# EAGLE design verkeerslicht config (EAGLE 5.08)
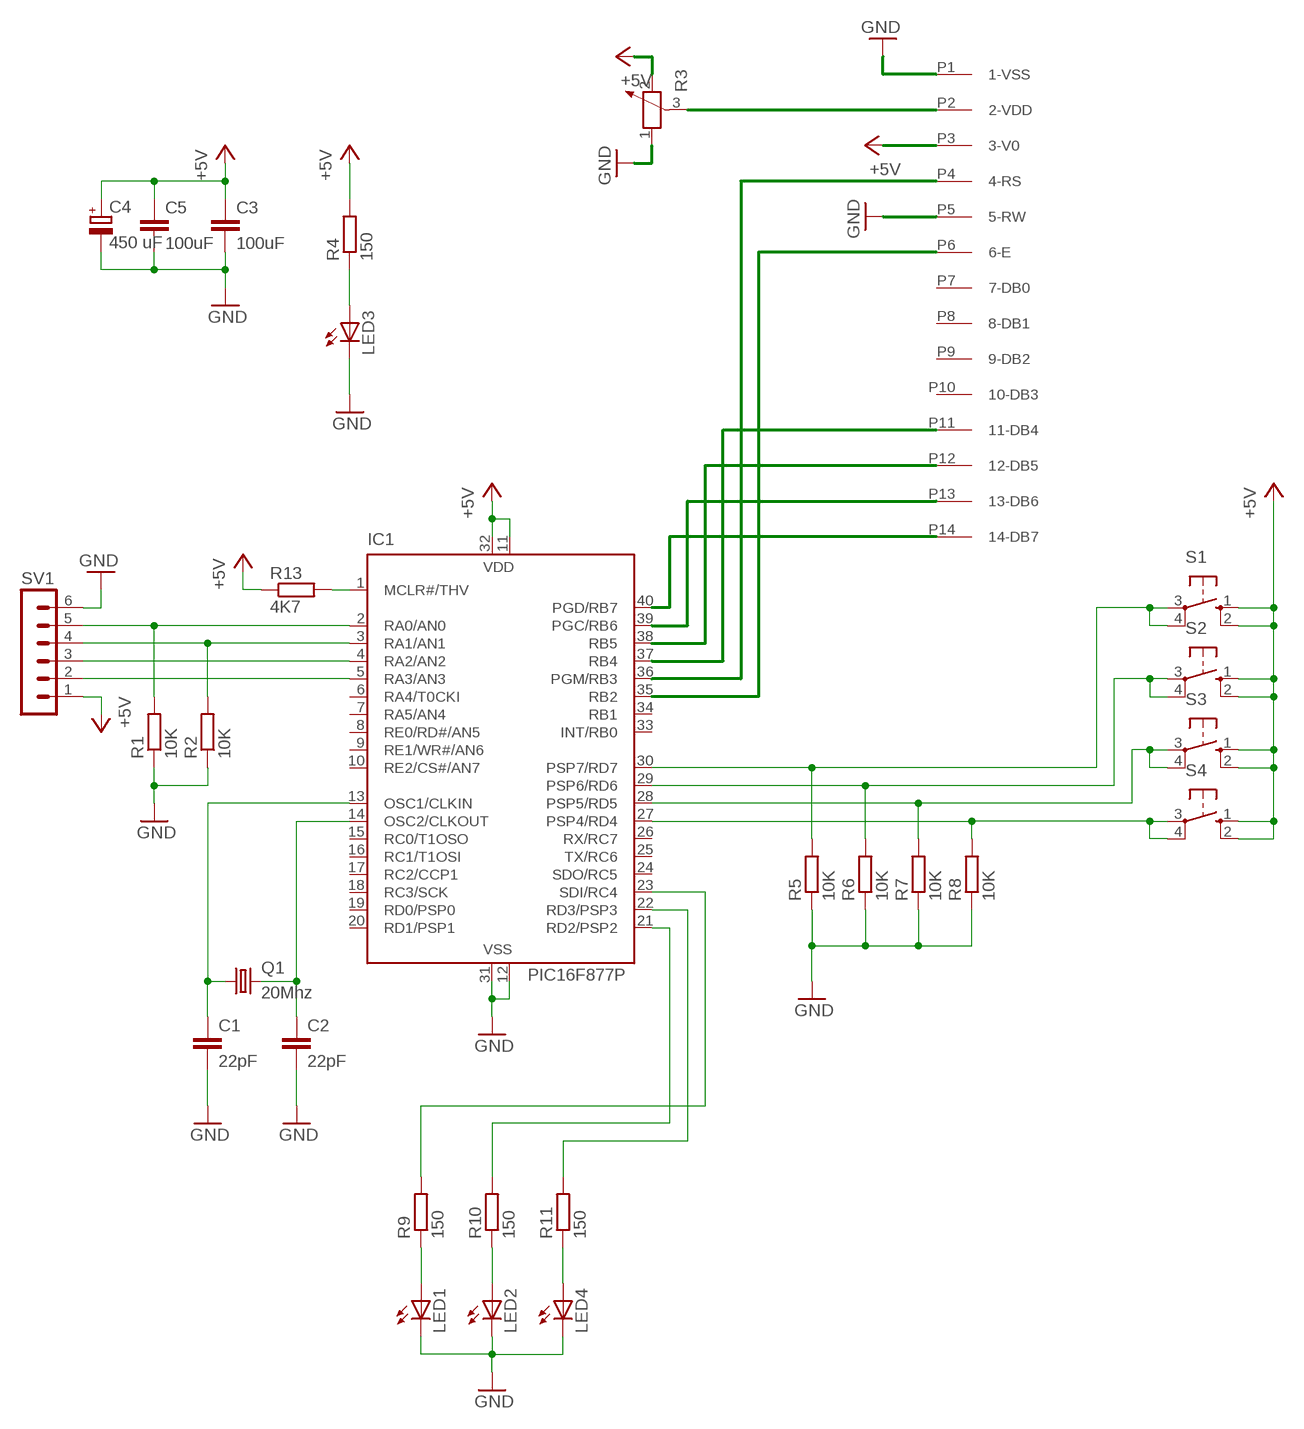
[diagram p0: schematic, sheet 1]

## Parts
C1  22pF  C-EU050-025X075  [C050-025X075]
C2  22pF  C-EU050-025X075  [C050-025X075]
C3  100uF  C-EU050-025X075  [C050-025X075]
C4  450 uF  CPOL-EUE5-13  [E5-13]
C5  100uF  C-EU050-025X075  [C050-025X075]
IC1  PIC16F877P  [DIL40]
LED1  LED3MM  [LED3MM]
LED2  LED3MM  [LED3MM]
LED3  LED3MM  [LED3MM]
LED4  LED3MM  [LED3MM]
Q1  20Mhz  CRYSTALHC18U-V  [HC18U-V]
R1  10K  R-EU_0207/7  [0207/7]
R2  10K  R-EU_0207/7  [0207/7]
R3  POTENTIOMETER_PT-10S  [PT-10S]
R4  150  R-EU_0207/7  [0207/7]
R5  10K  R-EU_0207/7  [0207/7]
R6  10K  R-EU_0207/7  [0207/7]
R7  10K  R-EU_0207/7  [0207/7]
R8  10K  R-EU_0207/7  [0207/7]
R9  150  R-EU_0207/2V  [0207/2V]
R10  150  R-EU_0207/2V  [0207/2V]
R11  150  R-EU_0207/2V  [0207/2V]
R13  4K7  R-EU_0207/10  [0207/10]
S1  10-XX  [B3F-10XX]
S2  10-XX  [B3F-10XX]
S3  10-XX  [B3F-10XX]
S4  10-XX  [B3F-10XX]
SV1  MA06-1  [MA06-1]
U$1  16X2LCD  [NO_BACKLIGHT]

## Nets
+5V: C3.1 C4.+ C5.1 IC1.11(VDD) IC1.32(VDD) R3.2 R4.2 R13.1 S1.1(S) S1.2(S1) S2.1(S) S2.2(S1) S3.1(S) S3.2(S1) S4.1(S) S4.2(S1) SV1.1 U$1.P3(3-V0)
GND: C1.2 C2.2 C3.2 C4.- C5.2 IC1.12(VSS) IC1.31(VSS) LED1.K(C) LED2.K(C) LED3.K(C) LED4.K(C) R1.1 R2.1 R3.1 R5.1 R6.1 R7.1 R8.1 SV1.6 U$1.P1(1-VSS) U$1.P5(5-RW)
N$1: IC1.23(SDI/RC4) R9.2
N$2: IC1.30(PSP7/RD7) R5.2 S1.3(P) S1.4(P1)
N$3: IC1.29(PSP6/RD6) R6.2 S2.3(P) S2.4(P1)
N$4: IC1.28(PSP5/RD5) R7.2 S3.3(P) S3.4(P1)
N$5: IC1.27(PSP4/RD4) R8.2 S4.3(P) S4.4(P1)
N$6: IC1.40(PGD/RB7) U$1.P14(14-DB7)
N$7: IC1.39(PGC/RB6) U$1.P13(13-DB6)
N$8: IC1.38(RB5) U$1.P12(12-DB5)
N$9: C1.1 IC1.13(OSC1/CLKIN) Q1.1
N$10: IC1.37(RB4) U$1.P11(11-DB4)
N$11: IC1.36(PGM/RB3) U$1.P4(4-RS)
N$12: IC1.35(RB2) U$1.P6(6-E)
N$13: R3.3 U$1.P2(2-VDD)
N$30: C2.1 IC1.14(OSC2/CLKOUT) Q1.2
N$31: IC1.1(MCLR#/THV) R13.2
N$33: IC1.21(RD2/PSP2) R10.2
N$34: LED3.A R4.1
N$35: LED1.A R9.1
N$36: LED2.A R10.1
N$53: IC1.2(RA0/AN0) R1.2 SV1.5
N$54: IC1.3(RA1/AN1) R2.2 SV1.4
N$55: IC1.4(RA2/AN2) SV1.3
N$56: IC1.5(RA3/AN3) SV1.2
N$72: LED4.A R11.1
N$73: IC1.22(RD3/PSP3) R11.2
Unconnected: IC1.6(RA4/T0CKI) IC1.7(RA5/AN4) IC1.8(RE0/RD#/AN5) IC1.9(RE1/WR#/AN6) IC1.10(RE2/CS#/AN7) IC1.15(RC0/T1OSO) IC1.16(RC1/T1OSI) IC1.17(RC2/CCP1) IC1.18(RC3/SCK) IC1.19(RD0/PSP0) IC1.20(RD1/PSP1) IC1.24(SDO/RC5) IC1.25(TX/RC6) IC1.26(RX/RC7) IC1.33(INT/RB0) IC1.34(RB1) U$1.P7(7-DB0) U$1.P8(8-DB1) U$1.P9(9-DB2) U$1.P10(10-DB3)

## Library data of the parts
C1-C3 C5 = rcl:C-EU: CAPACITOR, European symbol
C4 = rcl:CPOL-EU: POLARIZED CAPACITOR, European symbol
IC1 = microchip:PIC16F87*: MICROCONTROLLER
LED1-LED4 = led:LED: LED
Q1 = crystal:CRYSTAL: CRYSTAL
R1 R2 R4-R11 R13 = rcl:R-EU_: RESISTOR, European symbol
R3 = rcl:POTENTIOMETER_: Potentiometer
S1-S4 = switch-omron:10-XX: OMRON SWITCH
SV1 = con-lstb:MA06-1: PIN HEADER
U$1 = lcd_nobacklight:16X2LCD: 16x2 LCD - no backlight

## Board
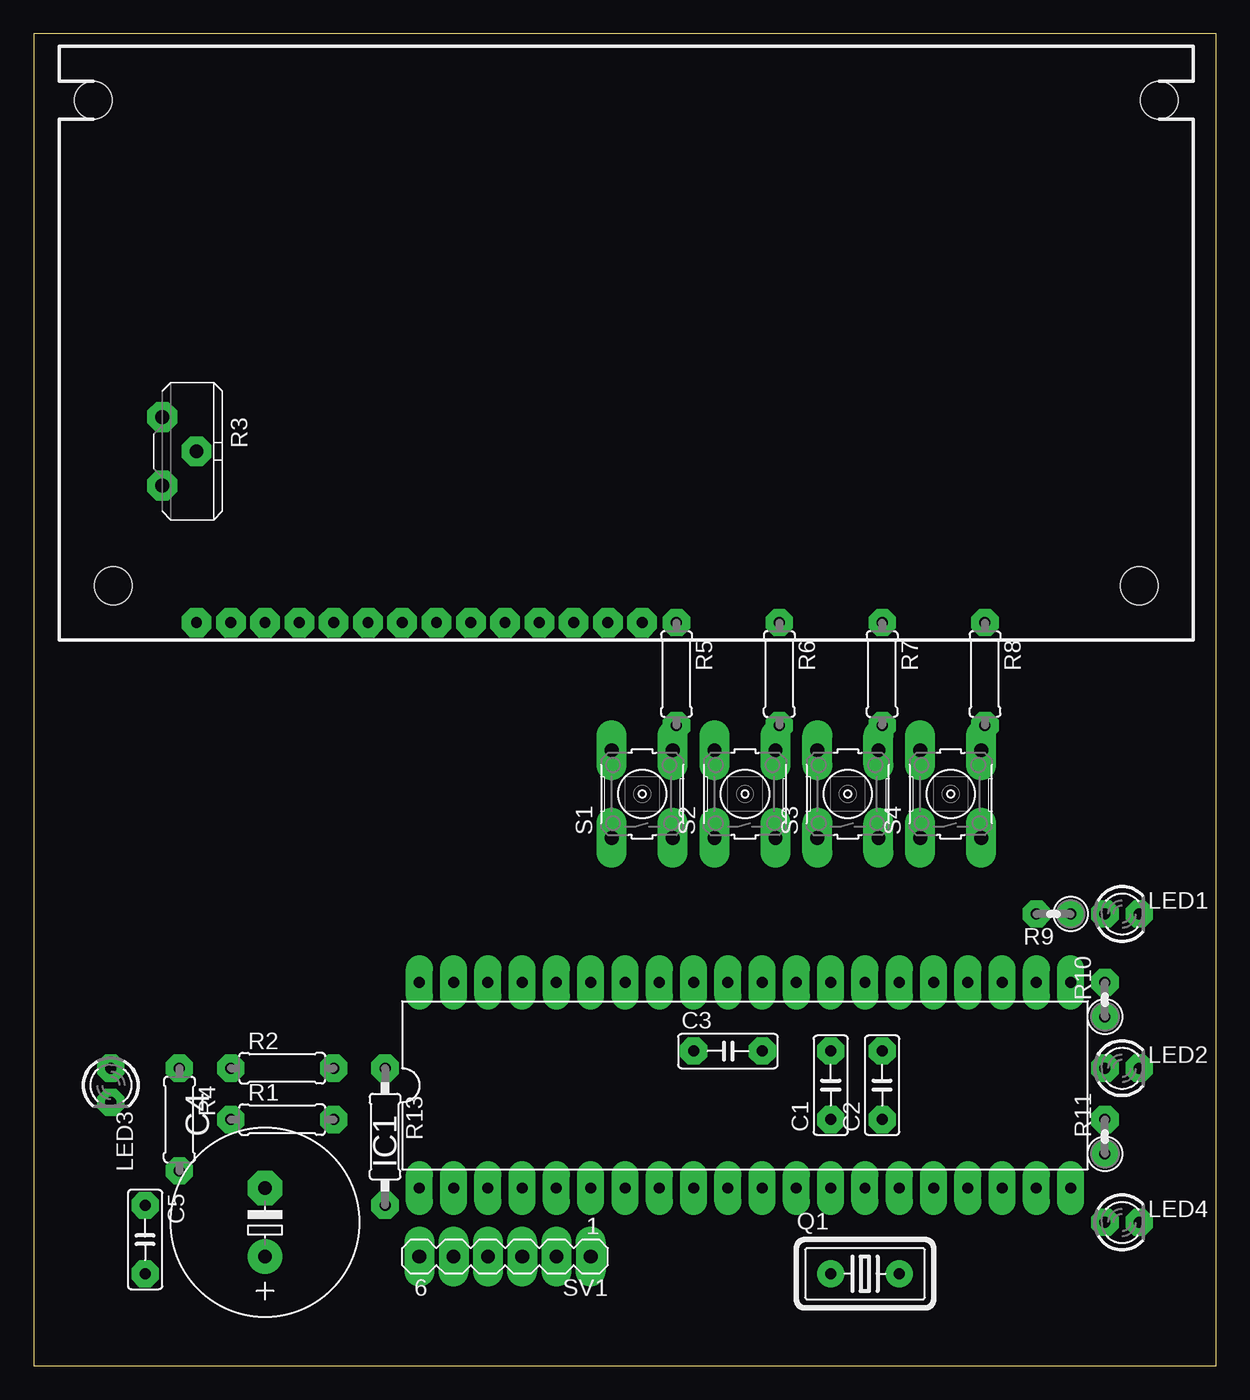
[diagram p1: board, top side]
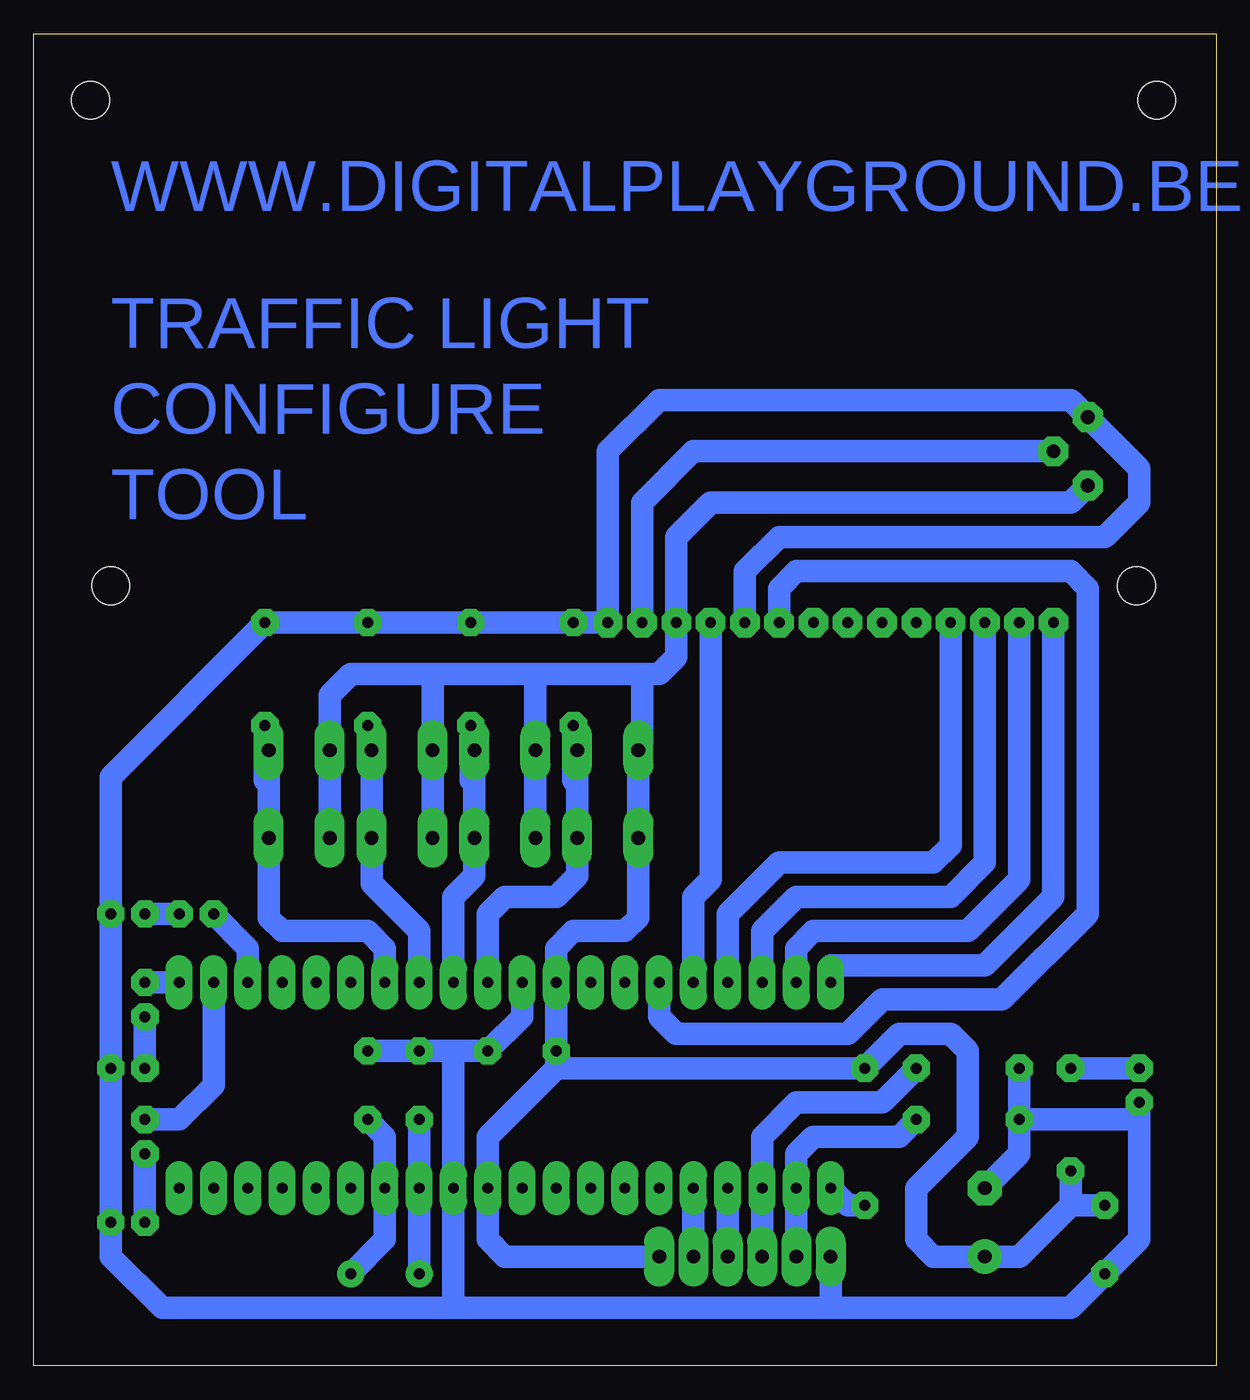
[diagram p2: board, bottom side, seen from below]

Size 87.61 x 98.73 mm. Coordinates in mm from the lower left corner, seen from the top.
Outline: 0,0 87.61,0 87.61,98.73 0,98.73 0,0
Copper layers (1*16): Top 1mm / dielectric 1.5mm / Bottom 1mm
Design rules "DRC settings middle": minimum track width 1.2mm, minimum drill 24mil, track to track 0.4mm, track to pad 0.4mm, pad to pad 0.4mm, via to via 0.4mm, smd to smd 8mil, copper to edge 0.5mm, drill to drill 0.5mm, minimum pad ring 0.6mm, minimum via ring 1mm, stop-mask expansion 4mil, vias tented up to drill 0mil, thermal gap 10mil

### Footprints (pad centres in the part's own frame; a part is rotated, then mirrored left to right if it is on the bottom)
C050-025X075 = drill 0.813 octagon: 1 -2.54,0; 2 2.54,0
E5-13 = drill 1.016 pad 2.54 round: + -2.54,0 | drill 1.016 pad 2.54 octagon: - 2.54,0
DIL40 = drill 0.813 long: 1 -24.13,-7.62; 2 -21.59,-7.62; 3 -19.05,-7.62; 4 -16.51,-7.62; 5 -13.97,-7.62; 6 -11.43,-7.62; 7 -8.89,-7.62; 8 -6.35,-7.62; 9 -3.81,-7.62; 10 -1.27,-7.62; 11 1.27,-7.62; 12 3.81,-7.62; 13 6.35,-7.62; 14 8.89,-7.62; 15 11.43,-7.62; 16 13.97,-7.62; 17 16.51,-7.62; 18 19.05,-7.62; 19 21.59,-7.62; 20 24.13,-7.62; 21 24.13,7.62; 22 21.59,7.62; 23 19.05,7.62; 24 16.51,7.62; 25 13.97,7.62; 26 11.43,7.62; 27 8.89,7.62; 28 6.35,7.62; 29 3.81,7.62; 30 1.27,7.62; 31 -1.27,7.62; 32 -3.81,7.62; 33 -6.35,7.62; 34 -8.89,7.62; 35 -11.43,7.62; 36 -13.97,7.62; 37 -16.51,7.62; 38 -19.05,7.62; 39 -21.59,7.62; 40 -24.13,7.62
LED3MM = drill 0.813 octagon: A -1.27,0; K 1.27,0
HC18U-V = drill 0.813 round: 1 -2.54,0; 2 2.54,0
0207/7 = drill 0.813 octagon: 1 -3.81,0; 2 3.81,0
PT-10S = drill 1.016 pad 1.778 octagon: 1 -2.54,-1.27; 2 2.54,-1.27; 3 0,1.27
0207/2V = drill 0.813 octagon: 1 -1.27,0; 2 1.27,0
0207/10 = drill 0.813 octagon: 1 -5.08,0; 2 5.08,0
B3F-10XX = drill 1.016 long: 1 -3.251,2.261; 2 3.251,2.261; 3 -3.251,-2.261; 4 3.251,-2.261
MA06-1 = drill 1.016 long: 1 -6.35,0; 2 -3.81,0; 3 -1.27,0; 4 1.27,0; 5 3.81,0; 6 6.35,0
NO_BACKLIGHT = drill 0.8 pad 2.184 octagon: P1 43.18,1.27; P2 40.64,1.27; P3 38.1,1.27; P4 35.56,1.27; P5 33.02,1.27; P6 30.48,1.27; P7 27.94,1.27; P8 25.4,1.27; P9 22.86,1.27; P10 20.32,1.27; P11 17.78,1.27; P12 15.24,1.27; P13 12.7,1.27; P14 10.16,1.27 | hole 2.8: 4,4; 80,4; 2.5,40; 81.5,40

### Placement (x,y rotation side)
C1  59.05,20.79 90 top
C2  62.86,20.79 90 top
C3  51.43,23.33 0 top
C4  17.14,10.63 90 top
C5  8.25,9.36 270 top
IC1  52.7,20.79 0 top
LED1  80.64,33.49 0 top
LED2  80.64,22.06 0 top
LED3  5.71,20.79 270 top
LED4  80.64,10.63 0 top
Q1  61.59,6.82 0 top
R1  18.41,18.25 0 top
R2  18.41,22.06 0 top
R3  10.79,67.78 270 top
R4  10.79,18.25 270 top
R5  47.62,51.27 270 top
R6  55.24,51.27 270 top
R7  62.86,51.27 270 top
R8  70.48,51.27 270 top
R9  75.56,33.49 180 top
R10  79.37,27.14 90 top
R11  79.37,16.98 90 top
R13  26.03,16.98 270 top
S1  45.08,42.38 90 top
S2  52.7,42.38 90 top
S3  60.32,42.38 90 top
S4  67.94,42.38 90 top
SV1  34.92,8.09 180 top
U$1  1.9,53.81 0 top

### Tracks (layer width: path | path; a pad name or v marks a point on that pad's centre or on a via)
+5V
  Bottom 1.676: SV1.1 52.7,8.09 53.97,9.36 IC1.11 53.97,16.98 48.89,22.06 | S2.1 S2.2 50.44,50.99 50.16,51.27 | S4.1 S4.2 65.68,49.72 64.13,51.27 57.78,51.27 | 10.79,11.9 14.6,8.09 C4.+ 20.95,8.09 22.22,9.36 22.22,13.17 18.41,16.98 18.41,23.33 19.68,24.6 23.49,24.6 R13.1 48.89,22.06 | C5.1 10.79,11.9 | 10.79,11.9 R4.2 | 48.89,22.06 C3.1 IC1.32 48.89,30.95 47.62,32.22 43.81,32.22 42.82,33.21 S1.1 S1.2 42.82,45.91 42.54,46.19 42.54,51.27 | 42.54,51.27 50.16,51.27 | 50.16,51.27 57.78,51.27 | 42.54,51.27 41.27,51.27 40,52.54 U$1.P3 40,61.43 37.46,63.97 10.79,63.97 R3.2 | 57.78,51.27 58.06,50.99 S3.2 S3.1
GND
  Bottom 1.676: IC1.31 51.43,25.87 C3.2 56.51,23.33 | 56.51,23.33 C1.2 C2.2 | 56.51,23.33 IC1.12 56.51,4.28 | R1.1 R2.1 | 28.57,4.28 56.51,4.28 | 56.51,4.28 78.1,4.28 81.91,8.09 LED4.K LED2.K LED1.K 81.91,43.65 R8.1 R7.1 R6.1 R5.1 U$1.P1 45.08,67.78 41.27,71.59 10.79,71.59 R3.1 5.71,66.51 5.71,63.97 8.25,61.43 32.38,61.43 34.92,58.89 U$1.P5 | 28.57,4.28 10.79,4.28 C5.2 5.71,9.36 5.71,18.25 | 28.57,4.28 SV1.6 | 5.71,18.25 LED3.K | 5.71,18.25 R1.1 | C4.- 14.6,15.71 R1.1
N$1
  Bottom 1.676: IC1.23 71.75,30.95 R9.2
N$2
  Bottom 1.676: IC1.30 53.97,33.49 52.7,34.76 48.89,34.76 47.34,36.31 S1.3 S1.4 47.62,43.37 R5.2
N$3
  Bottom 1.676: IC1.29 56.51,34.76 54.96,36.31 S2.3 S2.4 55.24,43.37 R6.2
N$4
  Bottom 1.676: IC1.28 59.05,32.22 62.58,35.75 S3.3 S3.4 62.58,47.18 R7.2
N$5
  Bottom 1.676: IC1.27 61.59,30.95 62.86,32.22 69.21,32.22 70.2,33.21 S4.3 S4.4 70.48,43.37 R8.2
N$6
  Bottom 1.676: U$1.P14 12.06,34.76 17.14,29.68 28.57,29.68 IC1.40
N$7
  Bottom 1.676: IC1.39 31.11,30.95 29.84,32.22 18.41,32.22 14.6,36.03 U$1.P13
N$8
  Bottom 1.676: IC1.38 33.65,32.22 31.11,34.76 19.68,34.76 17.14,37.3 U$1.P12
N$9
  Bottom 1.676: C1.1 IC1.13 59.05,9.36 Q1.1
N$10
  Bottom 1.676: IC1.37 36.19,33.49 32.38,37.3 20.95,37.3 19.68,38.57 U$1.P11
N$11
  Bottom 1.676: IC1.36 38.73,34.76 37.46,36.03 U$1.P4
N$12
  Bottom 1.676: IC1.35 41.27,25.87 40,24.6 27.3,24.6 24.76,27.14 15.87,27.14 9.52,33.49 9.52,57.62 10.79,58.89 31.11,58.89 32.38,57.62 U$1.P6
N$13
  Bottom 1.676: U$1.P2 42.54,63.97 38.73,67.78 R3.3
N$30
  Bottom 1.676: C2.1 61.59,16.98 IC1.14 61.59,9.36 Q1.2
N$31
  Bottom 1.676: R13.2 27.3,11.9 IC1.1
N$33
  Bottom 1.676: IC1.21 R10.2
N$34
  Bottom 1.676: LED3.A R4.1
N$35
  Bottom 1.676: R9.1 LED1.A
N$36
  Bottom 1.676: LED2.A R10.1
N$53
  Bottom 1.676: SV1.5 IC1.2 31.11,15.71 29.84,16.98 23.49,16.98 R1.2
N$54
  Bottom 1.676: SV1.4 IC1.3 33.65,16.98 31.11,19.52 24.76,19.52 R2.2
N$55
  Bottom 1.676: SV1.3 IC1.4
N$56
  Bottom 1.676: SV1.2 IC1.5
N$72
  Bottom 1.676: LED4.A R11.1
N$73
  Bottom 1.676: R11.2 76.83,18.25 74.29,20.79 IC1.22

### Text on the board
Bottom: WWW.DIGITALPLAYGROUND.BE | TRAFFIC LIGHT | CONFIGURE | TOOL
